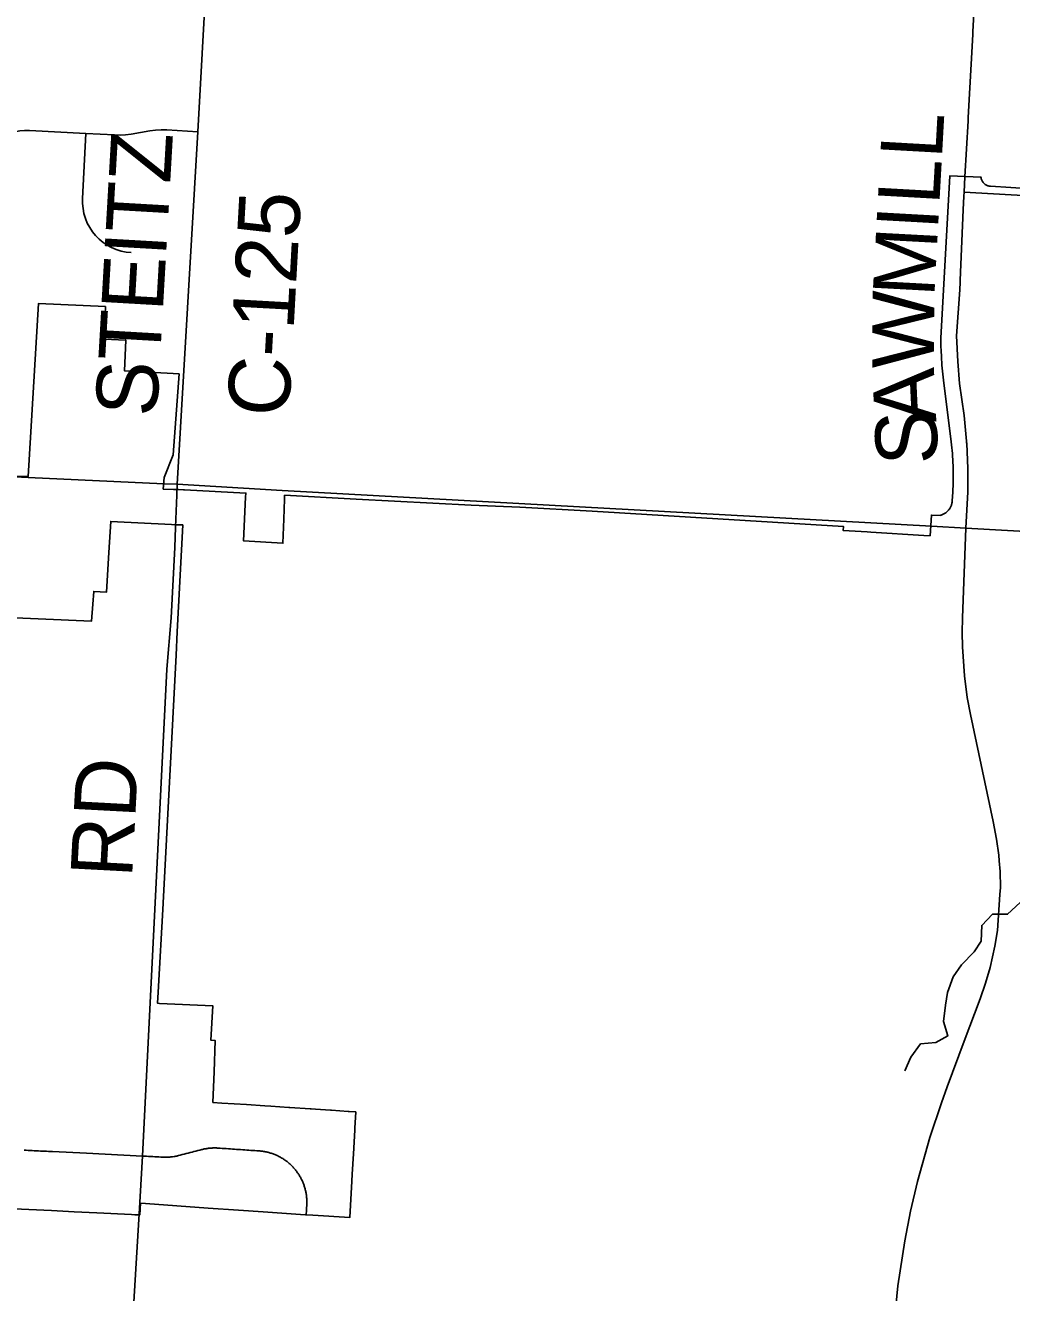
# Model space of a CAD drawing. Extents: x 114843 to 284848, y 317643 to 566895.
# Drawn here: x 174457 to 179255, y 468339 to 474500 of the extents above; entities that cross this region are included whole.
import ezdxf

# ---------------------------------------------------------------- set-up
doc = ezdxf.new("R2010")
doc.units = 0
for name, color, linetype in [('GM_X_Corporation', 7, 'Continuous'), ('GM_X_County_Road', 7, 'Continuous'), ('GM_X_County_Road_Text', 7, 'Continuous'), ('GM_X_Minor_River', 7, 'Continuous'), ('GM_X_Township_Road', 7, 'Continuous'), ('GM_X_Township_Road_Text', 7, 'Continuous')]:
    doc.layers.add(name, color=color, linetype=linetype)

msp = doc.modelspace()

# ---------------------------------------------------------------- linework, layer by layer
at = {"layer": 'GM_X_Corporation'}
for points in [[(174406, 472309), (174470.1, 472306.1), (174521.4, 473148), (174846.2, 473132.4), (174840.3, 472974.8), (174945.4, 472970.3), (174939.6, 472819.8), (175205.1, 472805.4), (175176, 472412), (175132.3, 472301.9), (175127.4, 472245.9), (175177.4, 472243.6), (175201.3, 472242.9), (175226.3, 472242.1), (175231.2, 472241.9), (175529.5, 472225.9), (175528.5, 472205.5), (175518.3, 471993.6), (175709.5, 471982.3), (175713.7, 472099.5), (175717.2, 472195.7), (175717.9, 472215.7), (176066.8, 472196.8), (176625.8, 472166.6), (176862.4, 472158.1), (177214.4, 472137.9), (178436.9, 472064), (178435.7, 472044.1), (178552.3, 472037), (178570.5, 472035.9), (178828.1, 472020.3), (178858.7, 472018.4), (178861.9, 472068.8), (178864.5, 472118.7), (178908.8, 472117.8), (178909.1, 472117.9), (178912.5, 472119), (178915.9, 472120.2), (178919.2, 472121.6), (178922.5, 472123.1), (178925.6, 472124.8), (178928.7, 472126.6), (178931.7, 472128.5), (178934.6, 472130.6), (178937.5, 472132.8), (178940.2, 472135.2), (178942.8, 472137.6), (178945.3, 472140.2), (178947.7, 472142.9), (178950, 472145.6), (178952.1, 472148.5), (178954.1, 472151.5), (178956, 472154.5), (178957.7, 472157.7), (178959.3, 472160.9), (178960.7, 472164.2), (178962, 472167.5), (178963.2, 472170.9), (178964.2, 472174.3), (178965, 472177.8), (178965.7, 472181.3), (178966.2, 472184.9), (178966.6, 472188.4), (178969.1, 472230.8), (178969.8, 472245.2), (178970.4, 472259.6), (178970.8, 472274), (178971.1, 472288.4), (178971.3, 472302.9), (178971.2, 472317.3), (178971.1, 472331.7), (178970.7, 472346.1), (178970.2, 472360.5), (178969.6, 472374.9), (178968.8, 472389.3), (178967.9, 472403.7), (178966.8, 472418.1), (178965.5, 472432.4), (178964.1, 472446.8), (178962.6, 472461.1), (178960.9, 472475.4), (178923.5, 472775.7), (178921.8, 472790), (178920.2, 472804.4), (178918.7, 472818.8), (178917.4, 472833.1), (178916.3, 472847.5), (178915.2, 472861.9), (178914.4, 472876.3), (178913.6, 472890.8), (178913.6, 472891.7), (178912.4, 472916.5), (178911.4, 472941.2), (178910.6, 472961.6), (178910, 472978.6), (178954.6, 473768.6), (179106.1, 473762.1), (179107, 473756.6), (179107.7, 473753.8), (179108.5, 473751.1), (179109.5, 473748.5), (179110.7, 473745.9), (179111.9, 473743.4), (179113.4, 473741), (179114.9, 473738.7), (179116.6, 473736.4), (179118.4, 473734.2), (179120.3, 473732.2), (179122.4, 473730.3), (179124.5, 473728.4), (179126.8, 473726.8), (179129.1, 473725.2), (179131.5, 473723.8), (179134, 473722.5), (179136.6, 473721.3), (179139.2, 473720.3), (179141.9, 473719.5), (179144.6, 473718.8), (179147.4, 473718.2), (179150.2, 473717.8), (179153, 473717.6), (179350.8, 473705.7)], [(174364.4, 468748.6), (174474.2, 468743.2), (174584.1, 468737.7), (174693.9, 468732.3), (174803.8, 468726.9), (174973.6, 468718.6), (174990.1, 468717.7), (175013.6, 468716.6), (175016.5, 468773.3), (175041.7, 468771.5), (175346.2, 468749.8), (175493.3, 468739.8), (175613.1, 468731.7), (175795.1, 468719.4), (175854.9, 468715.3), (176035.1, 468703.4), (176045.2, 468880.2), (176047.2, 468915.6), (176052.8, 469013.2), (176059.4, 469129.3), (176059.9, 469138.1), (176064.4, 469217.4), (176032.5, 469219.6), (176027.6, 469220), (175946.9, 469225.3), (175942, 469225.7), (175869, 469230.5), (175847.4, 469231.9), (175842.3, 469232.3), (175743.1, 469238.8), (175737.9, 469239.2), (175651.7, 469244.9), (175621.5, 469246.9), (175532, 469252.9), (175412.2, 469260.8), (175369.2, 469263.7), (175374.9, 469412.4), (175380.5, 469564.4), (175359.9, 469565.6), (175368.9, 469733.8), (175109.4, 469745.2), (175100.4, 469745.6), (175103.4, 469799.6), (175127.4, 470231.3), (175127.5, 470233.8), (175191.2, 471438.3), (175196.2, 471552.2), (175222.6, 472070.9), (175217.6, 472071.1), (175192.6, 472072.4), (175168.3, 472073.7), (174872.4, 472088.3), (174863.6, 471937.5), (174852.2, 471744.9), (174789.6, 471747.6), (174784.9, 471686.6), (174778.4, 471603.2), (174220.9, 471627.6)]]:
    msp.add_lwpolyline(points, dxfattribs=at)
at = {"layer": 'GM_X_County_Road'}
for p, q in [((179028.2, 473762.9), (179043.2, 474035.6)), ((174406.3, 472304.9), (174470.2, 472301.9)), ((174470.2, 472301.9), (175131, 472271.8)), ((178864.6, 472064.5), (179032.8, 472055.3))]:
    msp.add_line(p, q, dxfattribs=at)
for points in [[(175195, 472268.9), (175296.4, 473982.5), (175421.2, 476239.4), (175420.3, 476274.4), (175413.5, 476308.1), (175401, 476339.4), (175380.5, 476372.5), (175355.4, 476436), (175345, 476475), (175343, 476560.4), (175491.8, 478815.7), (175556.2, 479727.9)], [(179066.2, 474455), (179067.1, 474470.7), (179074.8, 474612.3), (179114.3, 475293), (179119.3, 475339.8)], [(179043.2, 474035.6), (179044, 474051.3), (179066.2, 474455)], [(179023.1, 473669.3), (179024.2, 473689.5), (179028.2, 473762.9)], [(179004.6, 473252), (179005, 473261.5), (179019.5, 473603.5), (179023.1, 473669.3)], [(179036, 472472.6), (179035.6, 472477.8), (179024.5, 472603), (179001.1, 472758.2), (178993.5, 472865.7), (178987.5, 472990.3), (179003, 473214.1), (179004.6, 473252)], [(179032.8, 472055.3), (179041.5, 472231.7), (179041.5, 472344.9), (179036.5, 472467.4), (179036, 472472.6)], [(175131, 472271.8), (175195, 472268.9), (175706.1, 472238.6), (178864.6, 472064.5)], [(178680.5, 468153.3), (178702.2, 468372.6), (178735.4, 468590.7), (178763.8, 468735.2), (178797.2, 468878.6), (178856.8, 469092.4), (178914.7, 469261.8), (178941.5, 469340.2), (179025, 469562.2), (179102.5, 469768), (179128.7, 469843.3), (179150.8, 469919.5), (179174.1, 470022.7), (179186.5, 470098.7), (179198.4, 470275.2), (179200.7, 470309.3), (179198.7, 470386.3), (179195, 470438.9), (179192.5, 470465.2), (179182.1, 470543.6), (179166.1, 470629.1), (179054.4, 471150.3), (179038.9, 471232.6), (179025.5, 471337.6), (179016.2, 471478.2), (179015.2, 471548.8), (179016.7, 471619.3), (179032.8, 472055.3)], [(179032.8, 472055.3), (179409.2, 472033.8), (179498.1, 472029.6)]]:
    msp.add_lwpolyline(points, dxfattribs=at)
at = {"layer": 'GM_X_Minor_River'}
for points in [[(179297.1, 470235.3), (179235.6, 470178.8), (179161.6, 470178.3), (179110.1, 470124), (179106.6, 470047.9), (179073.1, 469995.7), (179011.6, 469933.2)], [(179011.6, 469933.2), (178970, 469874.9), (178942.6, 469798.7), (178933.1, 469736.6), (178923.7, 469656.5), (178944.2, 469586.7), (178886.5, 469554.3), (178812.6, 469547.7), (178765.1, 469483.4), (178735.7, 469417.2)]]:
    msp.add_lwpolyline(points, dxfattribs=at)
at = {"layer": 'GM_X_Township_Road'}
for p, q in [((179024.2, 473689.5), (179395.6, 473667.4)), ((175193.1, 472216.7), (175195, 472268.9)), ((175187.6, 472060.4), (175193.1, 472216.7))]:
    msp.add_line(p, q, dxfattribs=at)
for points in [[(174282.1, 473913.1), (174299.7, 473929.4), (174318.7, 473943.9), (174339, 473956.5), (174360.4, 473967.2), (174382.7, 473975.9), (174405.7, 473982.4), (174429.2, 473986.8), (174453.1, 473988.9), (174477, 473988.8), (174751.6, 473974.4), (174890.4, 473967.1), (174917.6, 473966.7), (174944.7, 473968.2), (174971.7, 473971.7), (175062.4, 473986.9), (175090.1, 473990.4), (175118, 473991.9), (175145.9, 473991.3), (175296.4, 473982.5)], [(174971, 473395.1), (174946.7, 473397.7), (174922.7, 473402.6), (174899.3, 473409.8), (174876.7, 473419.3), (174855.1, 473431), (174834.8, 473444.7), (174816, 473460.3), (174798.7, 473477.7), (174783.3, 473496.7), (174769.8, 473517.1), (174758.3, 473538.8), (174749, 473561.4), (174742, 473584.9), (174737.3, 473608.9), (174735, 473633.3), (174735.1, 473657.8), (174751.6, 473974.4)], [(175010.2, 468721.6), (175026.9, 469002.7), (175145.3, 471370.7), (175165.5, 471619.3), (175184.1, 471961.3), (175187.6, 472060.4)], [(174450.6, 469031.3), (174460.5, 469030.8), (174470.4, 469030.3), (174480.4, 469029.8), (174490.3, 469029.3), (174500.2, 469028.9), (174510.1, 469028.4), (174520.1, 469027.9), (174530, 469027.4), (174539.9, 469026.9), (174549.8, 469026.4), (174559.8, 469025.9), (174569.7, 469025.4), (174579.6, 469025), (174589.5, 469024.5), (174753.6, 469016.3)], [(174753.6, 469016.3), (175026.9, 469002.7), (175036.8, 469002.1), (175046.7, 469001.6), (175056.6, 469001.1), (175066.5, 469000.6), (175076.4, 469000.1), (175086.4, 468999.5), (175096.3, 468999), (175106.1, 468998.5), (175116.1, 468998), (175126, 468997.5), (175130.2, 468997.3), (175134.4, 468997.2), (175138.6, 468997.2), (175142.8, 468997.2), (175147.1, 468997.3), (175151.3, 468997.5), (175155.5, 468997.7), (175159.7, 468998), (175163.9, 468998.4), (175168.1, 468998.9), (175172.3, 468999.4), (175180.6, 469000.6)], [(175180.6, 469000.6), (175184.8, 469001.4), (175188.9, 469002.2), (175193.1, 469003.1), (175197.2, 469004), (175201.3, 469005), (175210.8, 469007.5), (175220.3, 469009.9), (175229.7, 469012.4), (175239.2, 469014.8), (175248.7, 469017.2), (175258.2, 469019.7), (175267.7, 469022.1), (175277.2, 469024.6), (175286.7, 469027), (175296.2, 469029.5), (175305.6, 469031.9), (175315.1, 469034.4), (175319.2, 469035.4), (175323.4, 469036.3), (175327.5, 469037.2), (175331.7, 469038), (175335.8, 469038.7), (175340, 469039.4), (175344.2, 469040), (175348.4, 469040.5), (175352.6, 469041), (175356.8, 469041.4), (175361, 469041.7), (175365.2, 469041.9), (175369.5, 469042.1), (175373.7, 469042.2), (175377.9, 469042.3), (175382.2, 469042.2), (175386.4, 469042.1), (175390.6, 469041.9), (175394.8, 469041.7), (175404.8, 469040.9), (175414.7, 469040.3), (175424.7, 469039.6), (175434.6, 469038.9), (175444.6, 469038.2), (175454.5, 469037.5), (175464.4, 469036.8), (175474.4, 469036.1), (175484.3, 469035.4), (175494.3, 469034.7), (175504.2, 469034.1), (175514.1, 469033.3), (175524.1, 469032.7), (175534, 469032), (175544, 469031.3), (175553.9, 469030.6), (175563.9, 469029.9), (175573.8, 469029.2), (175583.8, 469028.5), (175593.7, 469027.8), (175598.1, 469027.5), (175602.4, 469027), (175606.7, 469026.6), (175611, 469026), (175615.4, 469025.4), (175619.7, 469024.6), (175624, 469023.9), (175628.2, 469023), (175632.5, 469022), (175636.7, 469021), (175640.9, 469019.9), (175645.1, 469018.8), (175649.3, 469017.5), (175653.5, 469016.2), (175657.6, 469014.8), (175661.7, 469013.4), (175665.8, 469011.9), (175669.9, 469010.3), (175673.9, 469008.6), (175677.9, 469006.9), (175681.8, 469005.1), (175685.8, 469003.2), (175689.7, 469001.3), (175693.6, 468999.3), (175697.4, 468997.2), (175701.2, 468995), (175705, 468992.8), (175708.7, 468990.5), (175712.3, 468988.2), (175716, 468985.8), (175719.6, 468983.3), (175723.1, 468980.8), (175726.6, 468978.2), (175730.1, 468975.6), (175733.5, 468972.9), (175736.9, 468970.1), (175740.2, 468967.3), (175743.5, 468964.4), (175746.7, 468961.5), (175749.8, 468958.5), (175752.9, 468955.4), (175756, 468952.3), (175759, 468949.1), (175762, 468945.9), (175764.8, 468942.7), (175767.7, 468939.4), (175770.5, 468936), (175773.2, 468932.6), (175775.8, 468929.1), (175778.4, 468925.6), (175781, 468922.1), (175783.4, 468918.5), (175785.8, 468914.8), (175788.2, 468911.2), (175790.5, 468907.5), (175792.7, 468903.7), (175794.8, 468899.9), (175796.9, 468896.1), (175799, 468892.2), (175800.9, 468888.3), (175802.8, 468884.4), (175804.6, 468880.4), (175806.4, 468876.4), (175808, 468872.4), (175809.6, 468868.4), (175811.2, 468864.3), (175812.6, 468860.2), (175814, 468856.1), (175815.3, 468851.9), (175816.6, 468847.7), (175817.8, 468843.5), (175818.8, 468839.3), (175819.9, 468835.1), (175820.8, 468830.8), (175821.7, 468826.6), (175822.5, 468822.3), (175823.2, 468818), (175823.9, 468813.6), (175824.5, 468809.3), (175825, 468805), (175825.4, 468800.7), (175825.7, 468796.3), (175826, 468792), (175826.2, 468787.6), (175826.3, 468783.2), (175826.4, 468778.9), (175826.4, 468774.6), (175826.2, 468770.2), (175826.1, 468765.8), (175825.8, 468761.5), (175825.1, 468752), (175824.5, 468742.5), (175823.9, 468733), (175823.2, 468723.6), (175822.6, 468714.1)], [(174952.6, 467626.9), (174976.9, 468159.5), (175010.2, 468721.6)]]:
    msp.add_lwpolyline(points, dxfattribs=at)

# ---------------------------------------------------------------- texts
at = {"layer": 'GM_X_County_Road_Text'}
for s, rotation, p in [('L', 86.80647, (178915.5, 473847.5)), ('STEITZ', 86.7083, (175095.9, 472593.5)), ('L', 86.80651, (178903.1, 473623.4)), ('C-125', 86.83642, (175738.3, 472593.2)), ('I', 86.80844, (178896.2, 473500.4)), ('M', 86.92271, (178878.7, 473175.5)), ('W', 89.68398, (178876.9, 472831.7)), ('A', 92.63564, (178889, 472572)), ('S', 92.86069, (178899.1, 472370.2))]:
    msp.add_text(s, height=300, rotation=rotation, dxfattribs=at).set_placement(p)
at = {"layer": 'GM_X_Township_Road_Text'}
msp.add_text('RD', height=300, rotation=86.95947, dxfattribs=at).set_placement((174975.7, 470352.5))

doc.saveas('drawing.dxf')
